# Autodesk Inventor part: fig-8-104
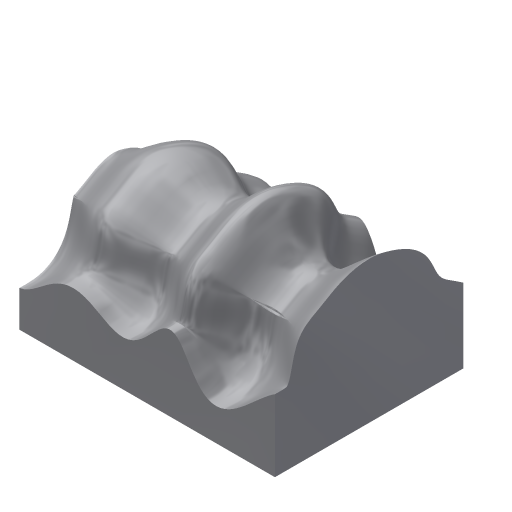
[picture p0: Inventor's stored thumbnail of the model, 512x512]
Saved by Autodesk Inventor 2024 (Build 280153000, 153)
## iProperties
Shininess: 64.0
Length Units: 11269
Angle Units: 11279
Time Units: 11290
Mass Units: 11283
Length Display Precision: 3
Angle Display Precision: 2
Compacted: True
Part Number: fig-8-104
Document SubType Name: Modeling
Created: 2002-12
Designer: deepak
Density: 1 g/cm^3
Material: Generic
Appearance: Aluminum - Flat
Density: 0.0
Volumn: 0.0
Area: 0.0
PropertySet Name: Model Information
Control State: 0
Master: False
Checked Out: False
Author: deepak
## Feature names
1. Extrusion1
## Parameters: d0 = 25 mm, d1 = 0, d2 = 0, d3 = 0
